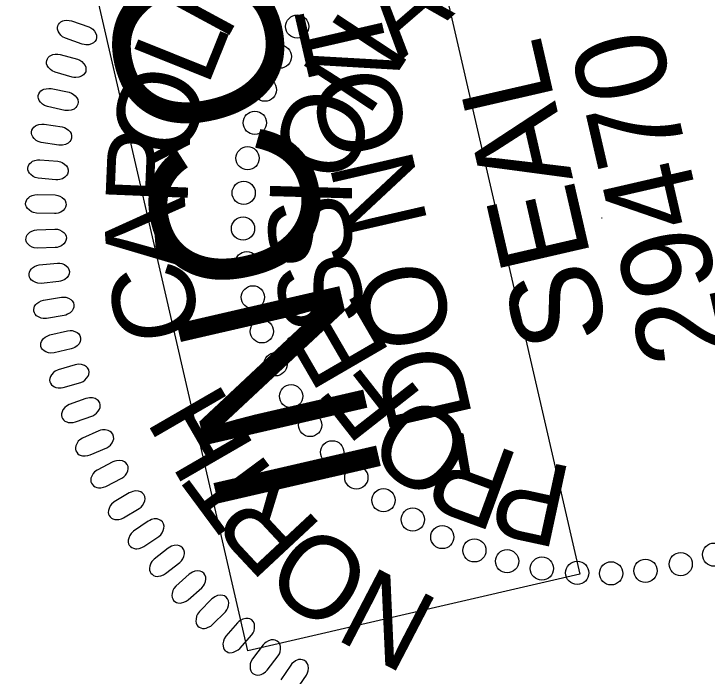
# Model space of a CAD drawing. Extents: x 480532 to 481977, y 491295 to 493182.
# Drawn here: x 480649.28 to 480697.14, y 492769.1 to 492814.8 of the extents above; entities that cross this region are included whole.
import ezdxf

# ---------------------------------------------------------------- set-up
doc = ezdxf.new("R2010")
doc.units = 0
doc.layers.add('Sheet PE Seal Cell', color=7, linetype='Continuous')
doc.layers.add('Sheet Sticker Incomplete CELL', color=7, linetype='Continuous')

msp = doc.modelspace()

# ---------------------------------------------------------------- linework, layer by layer
at = {"layer": 'Sheet PE Seal Cell'}
msp.add_line((480689.838, 492800.718), (480689.883, 492800.728), dxfattribs=at)
for points in [[(480653.997, 492812.705), (480652.84, 492813.113), (480652.646, 492813.221), (480652.532, 492813.317), (480652.409, 492813.479), (480652.337, 492813.607), (480652.3, 492813.739), (480652.297, 492813.851), (480652.316, 492813.964), (480652.372, 492814.063), (480652.44, 492814.165), (480652.531, 492814.245), (480652.66, 492814.31), (480652.755, 492814.34), (480652.919, 492814.354), (480653.108, 492814.35), (480653.265, 492814.318), (480654.453, 492813.907), (480654.605, 492813.829), (480654.722, 492813.74), (480654.843, 492813.603), (480654.937, 492813.451), (480654.981, 492813.333), (480654.985, 492813.164), (480654.953, 492813.017), (480654.866, 492812.89), (480654.784, 492812.807), (480654.648, 492812.72), (480654.448, 492812.664), (480654.256, 492812.661), (480654.124, 492812.676)], [(480653.304, 492810.433), (480652.124, 492810.767), (480651.924, 492810.863), (480651.804, 492810.952), (480651.671, 492811.106), (480651.592, 492811.229), (480651.546, 492811.359), (480651.536, 492811.471), (480651.547, 492811.584), (480651.597, 492811.686), (480651.659, 492811.793), (480651.745, 492811.878), (480651.869, 492811.951), (480651.962, 492811.987), (480652.124, 492812.011), (480652.314, 492812.019), (480652.473, 492811.998), (480653.684, 492811.662), (480653.841, 492811.594), (480653.963, 492811.513), (480654.092, 492811.383), (480654.196, 492811.237), (480654.246, 492811.122), (480654.261, 492810.954), (480654.24, 492810.805), (480654.161, 492810.672), (480654.084, 492810.585), (480653.953, 492810.49), (480653.757, 492810.421), (480653.566, 492810.405), (480653.433, 492810.412)], [(480652.792, 492808.135), (480651.593, 492808.395), (480651.387, 492808.478), (480651.262, 492808.559), (480651.12, 492808.704), (480651.033, 492808.822), (480650.979, 492808.949), (480650.962, 492809.06), (480650.966, 492809.174), (480651.01, 492809.279), (480651.064, 492809.39), (480651.145, 492809.479), (480651.265, 492809.56), (480651.355, 492809.602), (480651.516, 492809.636), (480651.704, 492809.656), (480651.865, 492809.645), (480653.094, 492809.385), (480653.255, 492809.328), (480653.382, 492809.254), (480653.519, 492809.132), (480653.632, 492808.993), (480653.689, 492808.881), (480653.715, 492808.715), (480653.702, 492808.565), (480653.631, 492808.428), (480653.561, 492808.336), (480653.436, 492808.233), (480653.245, 492808.152), (480653.055, 492808.124), (480652.923, 492808.123)], [(480652.386, 492805.741), (480651.173, 492805.925), (480650.962, 492805.996), (480650.831, 492806.068), (480650.68, 492806.205), (480650.586, 492806.317), (480650.525, 492806.44), (480650.501, 492806.549), (480650.498, 492806.663), (480650.534, 492806.771), (480650.582, 492806.885), (480650.657, 492806.979), (480650.771, 492807.068), (480650.859, 492807.115), (480651.017, 492807.159), (480651.203, 492807.191), (480651.365, 492807.19), (480652.608, 492807.008), (480652.772, 492806.96), (480652.904, 492806.895), (480653.048, 492806.782), (480653.17, 492806.651), (480653.234, 492806.543), (480653.269, 492806.378), (480653.266, 492806.227), (480653.204, 492806.086), (480653.139, 492805.99), (480653.022, 492805.879), (480652.836, 492805.787), (480652.648, 492805.746), (480652.516, 492805.737)], [(480652.182, 492803.351), (480650.96, 492803.459), (480650.745, 492803.516), (480650.611, 492803.58), (480650.451, 492803.706), (480650.351, 492803.813), (480650.281, 492803.931), (480650.251, 492804.039), (480650.24, 492804.153), (480650.27, 492804.263), (480650.311, 492804.379), (480650.379, 492804.479), (480650.488, 492804.573), (480650.573, 492804.626), (480650.728, 492804.68), (480650.912, 492804.724), (480651.073, 492804.732), (480652.325, 492804.629), (480652.492, 492804.593), (480652.627, 492804.535), (480652.779, 492804.432), (480652.907, 492804.307), (480652.978, 492804.204), (480653.024, 492804.042), (480653.031, 492803.891), (480652.978, 492803.746), (480652.919, 492803.647), (480652.809, 492803.529), (480652.63, 492803.425), (480652.445, 492803.373), (480652.313, 492803.355)], [(480652.082, 492801.019), (480650.855, 492801.05), (480650.637, 492801.093), (480650.498, 492801.149), (480650.332, 492801.265), (480650.225, 492801.364), (480650.148, 492801.479), (480650.111, 492801.584), (480650.093, 492801.697), (480650.116, 492801.808), (480650.149, 492801.927), (480650.211, 492802.03), (480650.314, 492802.132), (480650.395, 492802.19), (480650.546, 492802.254), (480650.727, 492802.309), (480650.888, 492802.328), (480652.144, 492802.304), (480652.312, 492802.276), (480652.451, 492802.228), (480652.608, 492802.135), (480652.745, 492802.019), (480652.823, 492801.92), (480652.878, 492801.762), (480652.894, 492801.612), (480652.85, 492801.463), (480652.798, 492801.36), (480652.696, 492801.235), (480652.523, 492801.12), (480652.342, 492801.057), (480652.212, 492801.031)], [(480652.138, 492798.666), (480650.912, 492798.62), (480650.691, 492798.649), (480650.55, 492798.696), (480650.376, 492798.802), (480650.263, 492798.895), (480650.179, 492799.004), (480650.135, 492799.107), (480650.111, 492799.218), (480650.127, 492799.331), (480650.152, 492799.452), (480650.208, 492799.558), (480650.304, 492799.667), (480650.381, 492799.729), (480650.528, 492799.802), (480650.705, 492799.869), (480650.864, 492799.898), (480652.119, 492799.952), (480652.289, 492799.936), (480652.431, 492799.896), (480652.594, 492799.813), (480652.737, 492799.706), (480652.821, 492799.612), (480652.886, 492799.458), (480652.912, 492799.309), (480652.878, 492799.158), (480652.832, 492799.052), (480652.737, 492798.921), (480652.572, 492798.795), (480652.396, 492798.721), (480652.267, 492798.686)], [(480652.384, 492796.322), (480651.164, 492796.199), (480650.941, 492796.214), (480650.798, 492796.252), (480650.618, 492796.347), (480650.498, 492796.433), (480650.408, 492796.536), (480650.357, 492796.636), (480650.327, 492796.746), (480650.336, 492796.86), (480650.353, 492796.981), (480650.402, 492797.091), (480650.491, 492797.205), (480650.564, 492797.273), (480650.706, 492797.356), (480650.879, 492797.432), (480651.035, 492797.471), (480652.285, 492797.605), (480652.456, 492797.599), (480652.599, 492797.569), (480652.767, 492797.495), (480652.917, 492797.398), (480653.006, 492797.31), (480653.081, 492797.159), (480653.117, 492797.012), (480653.092, 492796.86), (480653.053, 492796.75), (480652.966, 492796.614), (480652.809, 492796.478), (480652.637, 492796.393), (480652.511, 492796.35)], [(480652.744, 492793.981), (480651.534, 492793.781), (480651.311, 492793.782), (480651.165, 492793.811), (480650.979, 492793.895), (480650.855, 492793.972), (480650.758, 492794.07), (480650.702, 492794.167), (480650.664, 492794.275), (480650.666, 492794.388), (480650.676, 492794.511), (480650.718, 492794.624), (480650.799, 492794.744), (480650.868, 492794.815), (480651.005, 492794.907), (480651.172, 492794.994), (480651.325, 492795.043), (480652.565, 492795.254), (480652.735, 492795.26), (480652.88, 492795.238), (480653.052, 492795.175), (480653.208, 492795.088), (480653.303, 492795.005), (480653.388, 492794.86), (480653.432, 492794.715), (480653.417, 492794.561), (480653.384, 492794.45), (480653.306, 492794.308), (480653.159, 492794.163), (480652.993, 492794.067), (480652.869, 492794.017)], [(480653.248, 492791.676), (480652.053, 492791.401), (480651.831, 492791.388), (480651.682, 492791.408), (480651.492, 492791.479), (480651.364, 492791.549), (480651.261, 492791.641), (480651.198, 492791.733), (480651.154, 492791.839), (480651.148, 492791.952), (480651.15, 492792.075), (480651.185, 492792.19), (480651.259, 492792.315), (480651.324, 492792.392), (480651.454, 492792.49), (480651.616, 492792.589), (480651.766, 492792.647), (480652.989, 492792.936), (480653.159, 492792.952), (480653.305, 492792.94), (480653.481, 492792.888), (480653.643, 492792.81), (480653.742, 492792.733), (480653.835, 492792.593), (480653.888, 492792.452), (480653.883, 492792.298), (480653.858, 492792.185), (480653.789, 492792.038), (480653.65, 492791.884), (480653.491, 492791.778), (480653.371, 492791.72)], [(480653.508, 492790.591), (480652.332, 492790.242), (480652.132, 492790.143), (480652.014, 492790.053), (480651.882, 492789.897), (480651.805, 492789.773), (480651.761, 492789.643), (480651.752, 492789.531), (480651.765, 492789.418), (480651.816, 492789.316), (480651.879, 492789.21), (480651.966, 492789.127), (480652.092, 492789.055), (480652.185, 492789.021), (480652.348, 492788.998), (480652.537, 492788.992), (480652.696, 492789.016), (480653.903, 492789.368), (480654.059, 492789.437), (480654.18, 492789.52), (480654.307, 492789.651), (480654.409, 492789.799), (480654.458, 492789.914), (480654.471, 492790.083), (480654.447, 492790.231), (480654.366, 492790.363), (480654.288, 492790.449), (480654.156, 492790.543), (480653.96, 492790.609), (480653.768, 492790.622), (480653.636, 492790.614)], [(480654.253, 492788.261), (480653.101, 492787.838), (480652.908, 492787.727), (480652.795, 492787.63), (480652.674, 492787.466), (480652.605, 492787.337), (480652.569, 492787.205), (480652.568, 492787.092), (480652.587, 492786.98), (480652.645, 492786.882), (480652.714, 492786.78), (480652.806, 492786.703), (480652.936, 492786.638), (480653.031, 492786.61), (480653.195, 492786.598), (480653.384, 492786.604), (480653.542, 492786.638), (480654.724, 492787.064), (480654.875, 492787.144), (480654.991, 492787.234), (480655.11, 492787.373), (480655.202, 492787.526), (480655.243, 492787.645), (480655.246, 492787.813), (480655.213, 492787.961), (480655.124, 492788.087), (480655.041, 492788.168), (480654.904, 492788.253), (480654.704, 492788.307), (480654.512, 492788.308), (480654.38, 492788.291)], [(480655.146, 492786.023), (480654.024, 492785.529), (480653.838, 492785.406), (480653.731, 492785.302), (480653.621, 492785.131), (480653.56, 492784.999), (480653.532, 492784.864), (480653.538, 492784.752), (480653.564, 492784.641), (480653.628, 492784.546), (480653.704, 492784.449), (480653.8, 492784.377), (480653.934, 492784.321), (480654.031, 492784.299), (480654.195, 492784.298), (480654.383, 492784.315), (480654.539, 492784.359), (480655.691, 492784.859), (480655.838, 492784.947), (480655.948, 492785.045), (480656.057, 492785.191), (480656.14, 492785.35), (480656.174, 492785.471), (480656.165, 492785.639), (480656.123, 492785.784), (480656.026, 492785.905), (480655.939, 492785.98), (480655.796, 492786.056), (480655.593, 492786.098), (480655.402, 492786.087), (480655.271, 492786.062)], [(480656.124, 492783.883), (480655.035, 492783.319), (480654.857, 492783.185), (480654.757, 492783.074), (480654.658, 492782.897), (480654.606, 492782.76), (480654.586, 492782.624), (480654.598, 492782.512), (480654.632, 492782.404), (480654.701, 492782.313), (480654.783, 492782.221), (480654.884, 492782.156), (480655.021, 492782.109), (480655.119, 492782.092), (480655.283, 492782.101), (480655.47, 492782.13), (480655.622, 492782.183), (480656.742, 492782.755), (480656.882, 492782.852), (480656.985, 492782.957), (480657.086, 492783.11), (480657.158, 492783.273), (480657.184, 492783.396), (480657.166, 492783.564), (480657.114, 492783.705), (480657.01, 492783.82), (480656.918, 492783.89), (480656.771, 492783.957), (480656.565, 492783.985), (480656.375, 492783.962), (480656.247, 492783.929)], [(480657.253, 492781.748), (480656.201, 492781.117), (480656.032, 492780.973), (480655.94, 492780.856), (480655.852, 492780.673), (480655.807, 492780.533), (480655.797, 492780.396), (480655.816, 492780.285), (480655.857, 492780.179), (480655.932, 492780.092), (480656.019, 492780.006), (480656.124, 492779.947), (480656.263, 492779.908), (480656.363, 492779.898), (480656.526, 492779.917), (480656.71, 492779.958), (480656.859, 492780.021), (480657.94, 492780.661), (480658.074, 492780.768), (480658.17, 492780.878), (480658.261, 492781.037), (480658.323, 492781.205), (480658.342, 492781.329), (480658.312, 492781.495), (480658.252, 492781.633), (480658.141, 492781.741), (480658.044, 492781.805), (480657.894, 492781.863), (480657.687, 492781.878), (480657.499, 492781.843), (480657.372, 492781.802)], [(480658.543, 492779.787), (480657.533, 492779.091), (480657.373, 492778.936), (480657.288, 492778.814), (480657.212, 492778.625), (480657.177, 492778.483), (480657.175, 492778.346), (480657.201, 492778.237), (480657.249, 492778.133), (480657.329, 492778.052), (480657.421, 492777.97), (480657.53, 492777.918), (480657.671, 492777.888), (480657.771, 492777.885), (480657.932, 492777.914), (480658.114, 492777.967), (480658.258, 492778.038), (480659.297, 492778.745), (480659.424, 492778.86), (480659.513, 492778.976), (480659.594, 492779.141), (480659.645, 492779.312), (480659.656, 492779.437), (480659.616, 492779.601), (480659.547, 492779.735), (480659.43, 492779.835), (480659.33, 492779.893), (480659.175, 492779.942), (480658.968, 492779.944), (480658.782, 492779.897), (480658.658, 492779.848)], [(480659.928, 492777.933), (480658.963, 492777.176), (480658.814, 492777.011), (480658.736, 492776.883), (480658.672, 492776.69), (480658.646, 492776.546), (480658.653, 492776.409), (480658.686, 492776.301), (480658.739, 492776.201), (480658.824, 492776.125), (480658.922, 492776.05), (480659.033, 492776.004), (480659.177, 492775.983), (480659.276, 492775.986), (480659.435, 492776.025), (480659.614, 492776.089), (480659.753, 492776.17), (480660.745, 492776.941), (480660.865, 492777.063), (480660.947, 492777.185), (480661.017, 492777.354), (480661.058, 492777.529), (480661.06, 492777.654), (480661.01, 492777.815), (480660.934, 492777.945), (480660.81, 492778.037), (480660.706, 492778.089), (480660.549, 492778.127), (480660.342, 492778.117), (480660.159, 492778.058), (480660.039, 492778.002)], [(480661.384, 492776.131), (480660.469, 492775.314), (480660.329, 492775.14), (480660.26, 492775.009), (480660.208, 492774.812), (480660.191, 492774.666), (480660.206, 492774.53), (480660.247, 492774.425), (480660.306, 492774.328), (480660.395, 492774.258), (480660.498, 492774.188), (480660.612, 492774.15), (480660.756, 492774.138), (480660.856, 492774.147), (480661.012, 492774.196), (480661.186, 492774.271), (480661.32, 492774.361), (480662.262, 492775.192), (480662.374, 492775.322), (480662.448, 492775.448), (480662.507, 492775.621), (480662.537, 492775.798), (480662.532, 492775.924), (480662.472, 492776.081), (480662.387, 492776.205), (480662.258, 492776.29), (480662.151, 492776.335), (480661.992, 492776.364), (480661.786, 492776.34), (480661.607, 492776.271), (480661.49, 492776.206)], [(480662.95, 492774.422), (480662.088, 492773.549), (480661.96, 492773.366), (480661.899, 492773.231), (480661.859, 492773.031), (480661.852, 492772.885), (480661.876, 492772.75), (480661.922, 492772.647), (480661.988, 492772.555), (480662.081, 492772.489), (480662.188, 492772.427), (480662.304, 492772.396), (480662.449, 492772.393), (480662.547, 492772.408), (480662.701, 492772.467), (480662.869, 492772.554), (480662.998, 492772.651), (480663.886, 492773.54), (480663.989, 492773.676), (480664.055, 492773.808), (480664.103, 492773.984), (480664.121, 492774.162), (480664.109, 492774.287), (480664.039, 492774.44), (480663.946, 492774.559), (480663.812, 492774.636), (480663.702, 492774.674), (480663.542, 492774.693), (480663.338, 492774.655), (480663.163, 492774.575), (480663.052, 492774.504)], [(480664.719, 492772.777), (480663.914, 492771.851), (480663.798, 492771.661), (480663.745, 492771.522), (480663.718, 492771.32), (480663.72, 492771.174), (480663.752, 492771.04), (480663.805, 492770.941), (480663.877, 492770.853), (480663.974, 492770.794), (480664.084, 492770.738), (480664.202, 492770.714), (480664.347, 492770.721), (480664.444, 492770.742), (480664.593, 492770.811), (480664.756, 492770.906), (480664.878, 492771.012), (480665.708, 492771.955), (480665.803, 492772.098), (480665.861, 492772.233), (480665.898, 492772.412), (480665.905, 492772.59), (480665.884, 492772.715), (480665.805, 492772.863), (480665.705, 492772.976), (480665.566, 492773.044), (480665.455, 492773.075), (480665.293, 492773.084), (480665.092, 492773.034), (480664.923, 492772.943), (480664.815, 492772.865)], [(480666.495, 492771.256), (480665.749, 492770.282), (480665.646, 492770.086), (480665.602, 492769.943), (480665.588, 492769.74), (480665.598, 492769.594), (480665.639, 492769.462), (480665.698, 492769.367), (480665.775, 492769.283), (480665.876, 492769.231), (480665.99, 492769.182), (480666.109, 492769.165), (480666.253, 492769.181), (480666.349, 492769.208), (480666.493, 492769.286), (480666.65, 492769.392), (480666.765, 492769.506), (480667.534, 492770.498), (480667.619, 492770.647), (480667.669, 492770.785), (480667.694, 492770.966), (480667.69, 492771.145), (480667.662, 492771.268), (480667.573, 492771.411), (480667.466, 492771.517), (480667.324, 492771.576), (480667.211, 492771.6), (480667.049, 492771.598), (480666.851, 492771.536), (480666.689, 492771.435), (480666.586, 492771.35)]]:
    msp.add_lwpolyline(points, close=True, dxfattribs=at)
msp.add_lwpolyline([(480668.774, 492768.129), (480669.481, 492769.169), (480669.557, 492769.322), (480669.597, 492769.463), (480669.611, 492769.645), (480669.596, 492769.825), (480669.56, 492769.945), (480669.463, 492770.082), (480669.349, 492770.182), (480669.203, 492770.231), (480669.088, 492770.249), (480668.927, 492770.237), (480668.734, 492770.163), (480668.578, 492770.05), (480668.481, 492769.96), (480668.396, 492769.86), (480667.713, 492768.841)], dxfattribs=at)
for centre in [(480668.843, 492813.92), (480667.645, 492811.847), (480666.616, 492809.567), (480665.916, 492807.281), (480665.415, 492804.838), (480665.148, 492802.447), (480665.101, 492799.985), (480665.365, 492797.595), (480665.785, 492795.24), (480666.407, 492792.891), (480667.34, 492790.614), (480668.42, 492788.411), (480669.735, 492786.426), (480671.257, 492784.545), (480672.925, 492782.805), (480674.799, 492781.234), (480676.822, 492779.902), (480678.858, 492778.696), (480681.073, 492777.776), (480697.619, 492777.483), (480683.33, 492777.029), (480695.317, 492776.83), (480685.736, 492776.521), (480692.884, 492776.368), (480688.175, 492776.224), (480690.513, 492776.19)]:
    msp.add_circle(centre, 0.801, dxfattribs=at)
at = {"layer": 'Sheet Sticker Incomplete CELL'}
msp.add_lwpolyline([(480688.341, 492776.127), (480665.442, 492770.848), (480632.421, 492914.091), (480655.321, 492919.37)], close=True, dxfattribs=at)

# ---------------------------------------------------------------- texts
at = {"layer": 'Sheet PE Seal Cell'}
for s, height, rotation, p in [('A', 5.669, 40.7518, (480675.954, 492811.531)), ('I', 5.669, 61.6327, (480663.836, 492812.73)), ('N', 5.669, 56.6314, (480673.702, 492807.587)), ('L', 5.669, 68.122, (480662.635, 492809.69)), ('SEAL', 6.2363, 102.9625, (480690.384, 492792.591)), ('29470', 6.2363, 102.9625, (480698.924, 492791.51)), ('O', 5.669, 74.6114, (480661.232, 492804.509)), ('O', 5.669, 72.511, (480672.425, 492802.868)), ('R', 5.669, 87.5901, (480661.258, 492801.483)), ('I', 5.669, 88.3906, (480672.595, 492801.364)), ('A', 5.669, 94.0794, (480661.429, 492797.205)), ('S', 5.669, 96.3303, (480672.833, 492797.519)), ('S', 5.669, 104.2701, (480673.799, 492793.78)), ('C', 5.669, 100.5688, (480662.254, 492792.7)), ('E', 5.669, 120.1497, (480675.356, 492791.299)), ('F', 5.669, 128.0895, (480677.617, 492788.341)), ('H', 5.669, 120.0369, (480666, 492784.835)), ('O', 5.669, 143.9691, (480681.506, 492785.443)), ('R', 5.669, 159.8487, (480684.372, 492784.345)), ('T', 5.669, 126.5262, (480668.088, 492782.054)), ('P', 5.669, 167.7885, (480688.027, 492783.457)), ('R', 5.669, 133.0156, (480670.681, 492779.347)), ('O', 5.669, 145.9943, (480674.413, 492776.64)), ('N', 5.669, 152.4836, (480678.823, 492774.223))]:
    msp.add_text(s, height=height, rotation=rotation, dxfattribs=at).set_placement(p)
at = {"layer": 'Sheet Sticker Incomplete CELL'}
for s, height, p in [('INCOMPLETE PLANS', 11.52, (480674.93, 492782.22)), ('DO NOT USE FOR R/W ACQUISITION', 5.76, (480680.972, 492786.948))]:
    msp.add_text(s, height=height, rotation=102.9811, dxfattribs=at).set_placement(p)

doc.saveas('drawing.dxf')
